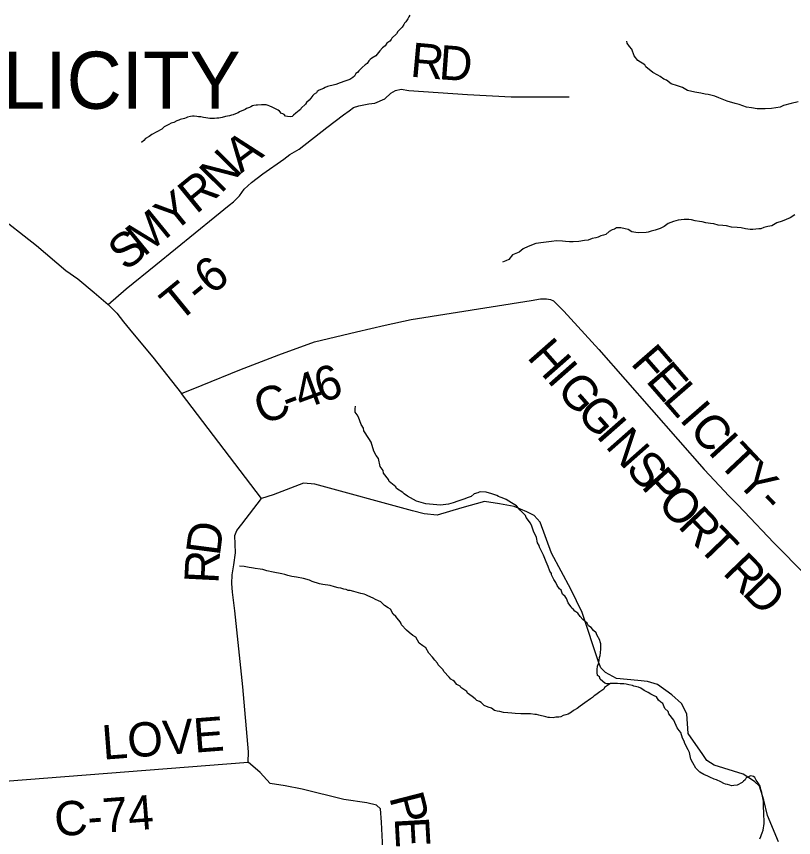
# Model space of a CAD drawing. Extents: x 1310247 to 1664935, y 235267 to 584339.
# Drawn here: x 1516027 to 1522829, y 302982 to 310168 of the extents above; entities that cross this region are included whole.
import ezdxf

# ---------------------------------------------------------------- set-up
doc = ezdxf.new("R2010")
doc.units = 0
for name, color, linetype in [('GM_X_Corporation_Text', 7, 'Continuous'), ('GM_X_County_Road', 7, 'Continuous'), ('GM_X_County_Road_Text', 7, 'Continuous'), ('GM_X_Minor_River', 7, 'Continuous'), ('GM_X_Township_Road', 7, 'Continuous'), ('GM_X_Township_Road_Text', 7, 'Continuous')]:
    doc.layers.add(name, color=color, linetype=linetype)

msp = doc.modelspace()

# ---------------------------------------------------------------- linework, layer by layer
at = {"layer": 'GM_X_County_Road'}
for points in [[(1515830, 308454), (1515834.2, 308450.8), (1516203.6, 308162.7), (1516460.4, 307945.9), (1516564.5, 307871.7), (1516707.1, 307751.9), (1516829.7, 307647.2), (1516905.4, 307570.7), (1516965.3, 307495.2), (1517043.7, 307398.2), (1517219.2, 307187), (1517470.2, 306867.6)], [(1517470.2, 306867.6), (1517651.3, 306940.3), (1517982.2, 307074.4), (1518324.6, 307205.6), (1518635.5, 307319.7), (1519003, 307408.2), (1519252.7, 307465.8), (1519482.6, 307516.8), (1520531.6, 307682.4), (1520613.6, 307695.7), (1520665, 307697.3), (1520701.4, 307690.6), (1520726.2, 307680), (1520817.9, 307588), (1521122.7, 307254.6), (1522045.4, 306204.2), (1522180.8, 306059.4), (1522260.7, 305974), (1522337.2, 305896.4), (1522396.1, 305834.8), (1522656.5, 305562.8), (1522936.1, 305279.3)], [(1518170.5, 305950.4), (1517470.2, 306867.6)], [(1522697.7, 302946.6), (1522600.7, 303174.8), (1522569.3, 303308.9), (1522529, 303431), (1522487.8, 303474.4), (1522386.7, 303537.1), (1522132.8, 303617), (1522069.4, 303656), (1522033, 303708.3), (1521904.6, 303893.7), (1521893.2, 304064.8), (1521847.5, 304155.6), (1521762, 304230.3), (1521636.5, 304321.6), (1521548.8, 304348.1), (1521465.3, 304355.8), (1521279.9, 304375.8), (1521182.9, 304427.1), (1521142.8, 304468), (1521123, 304512.7), (1520977.5, 304952), (1520879.9, 305155.8), (1520709.4, 305471.2), (1520609.5, 305742.2), (1520558, 305799.5), (1520492.6, 305833.5), (1520384.2, 305879.1), (1520255.8, 305901.9), (1520124.6, 305924.7), (1519924.9, 305867.7), (1519708.1, 305805), (1519594.7, 305814.2), (1519494.1, 305842), (1518638.4, 306076), (1518538.5, 306084.5), (1518273.2, 305981.8), (1518170.5, 305950.4)], [(1515927.5, 303476), (1518053.6, 303643.7), (1518056.6, 303733.7), (1518008.3, 304301.7), (1517938.3, 304965.4), (1517917.1, 305130.3), (1517912.7, 305205), (1517913.8, 305283), (1517930.5, 305368.8), (1517942.8, 305474.7), (1517937.4, 305626.6), (1517956.2, 305668.3), (1517999.4, 305725.7), (1518170.5, 305950.4)]]:
    msp.add_lwpolyline(points, dxfattribs=at)
at = {"layer": 'GM_X_Minor_River'}
for points in [[(1519471.2, 310178.1), (1519461, 310166.2), (1519452.8, 310146.2), (1519434.4, 310122.3), (1519424.2, 310108.4), (1519416, 310096.5), (1519403.7, 310074.5), (1519365.1, 310036.8), (1519352.8, 310014.9), (1519312.2, 309977.2), (1519306, 309965.2), (1519295.9, 309953.3), (1519269.5, 309933.5), (1519255.2, 309911.6), (1519230.9, 309893.8), (1519206.5, 309868), (1519171.8, 309822.3), (1519137.4, 309802.6), (1519123.3, 309792.8), (1519111.1, 309780.8), (1519096.7, 309756.9), (1519078.5, 309745.1), (1519054.1, 309721.3), (1519023.7, 309691.5), (1519011.4, 309677.6), (1518997.3, 309669.8), (1518987, 309645.8), (1518970.8, 309633.9), (1518944.4, 309616.2), (1518928.3, 309610.4), (1518902.1, 309602.6), (1518859.8, 309587.1), (1518821.4, 309573.5), (1518809.4, 309569.6), (1518748.9, 309554.3), (1518728.8, 309546.6), (1518714.6, 309538.7), (1518676.3, 309523.1), (1518658.1, 309511.3), (1518651.9, 309499.3), (1518633.7, 309487.5), (1518621.5, 309475.6), (1518603.1, 309453.7), (1518588.9, 309435.8), (1518566.5, 309414), (1518556.4, 309402), (1518519.8, 309366.3), (1518513.6, 309354.4), (1518501.5, 309344.5), (1518471, 309320.8), (1518452.8, 309304.9), (1518440.6, 309293), (1518424.5, 309289.2), (1518398.4, 309291.5), (1518382.4, 309295.7), (1518370.5, 309310), (1518358.5, 309316.1), (1518346.5, 309320.3), (1518330.7, 309338.6), (1518316.8, 309348.8), (1518264.9, 309375.5), (1518244.9, 309383.8), (1518228.9, 309390), (1518212.9, 309394.2), (1518172.7, 309394.8), (1518136.5, 309391.2), (1518124.5, 309391.3), (1518104.4, 309387.5), (1518092.3, 309385.7), (1518078.1, 309375.8), (1518066, 309370), (1518039.8, 309362.2), (1518027.6, 309354.4), (1517979.2, 309332.9), (1517967.1, 309325), (1517942.9, 309317.2), (1517924.7, 309307.4), (1517908.6, 309303.6), (1517890.4, 309299.8), (1517856.2, 309292.2), (1517828, 309282.5), (1517797.8, 309276.8), (1517779.7, 309277.1), (1517761.6, 309275.3), (1517719.5, 309275.8), (1517683.4, 309280.3), (1517665.4, 309284.5), (1517639.3, 309288.9)], [(1522870, 309420.7), (1522807.6, 309407.4), (1522741.1, 309388.1), (1522710.9, 309374.5), (1522634.4, 309361.3), (1522580.2, 309360), (1522509.9, 309358.9), (1522459.8, 309367.5), (1522417.7, 309374.1), (1522353.7, 309397), (1522317.6, 309407.5), (1522247.6, 309426.5), (1522173.6, 309455.5), (1522139.7, 309472), (1522079.6, 309484.8), (1522053.5, 309489.1), (1522015.5, 309495.6), (1521965.4, 309504.3), (1521901.3, 309519.1), (1521855.4, 309547.8), (1521813.4, 309560.4), (1521757.4, 309579.2), (1521717.6, 309611.8), (1521693.6, 309620.2), (1521661.8, 309642.6), (1521641.8, 309653), (1521597.9, 309677.6), (1521536.2, 309726.6), (1521526.4, 309744.8), (1521464.6, 309781.7), (1521433, 309822.3), (1521411.6, 309882.8), (1521391.8, 309905.1), (1521372, 309933.5), (1521370.2, 309951.6)], [(1517639.3, 309288.9), (1517619.2, 309291.1), (1517607.2, 309293.3), (1517583.2, 309295.6), (1517569.1, 309295.7), (1517549, 309294), (1517524.8, 309286.2), (1517512.7, 309282.4), (1517496.6, 309276.5), (1517460.3, 309267), (1517448.2, 309261.1), (1517430, 309253.3), (1517405.8, 309239.5), (1517381.6, 309233.8), (1517361.4, 309224), (1517321, 309202.4), (1517298.7, 309182.6), (1517211.8, 309135.5), (1517189.5, 309117.6), (1517157.1, 309100), (1517142.8, 309082.1), (1517122.6, 309064.2)], [(1522840.2, 308430.8), (1522797.8, 308407.3), (1522727.2, 308378), (1522680.8, 308362.5), (1522638.3, 308337), (1522604.1, 308331.4), (1522567.9, 308321.8), (1522541.6, 308310.1), (1522523.5, 308308.3), (1522499.4, 308306.6), (1522471.3, 308304.9), (1522449.2, 308305.2), (1522409.1, 308309.7), (1522369, 308318.2), (1522334.9, 308320.7), (1522284.7, 308325.3), (1522242.7, 308335.9), (1522210.6, 308338.3), (1522168.5, 308342.8), (1522130.4, 308353.4), (1522100.4, 308355.7), (1522060.3, 308362.3), (1522028.2, 308370.7), (1522004.2, 308375), (1521966.1, 308379.5), (1521936.1, 308387.9), (1521912, 308390.2), (1521871.8, 308390.7), (1521819.6, 308385.4), (1521777.3, 308373.8), (1521730.9, 308356.3), (1521696.4, 308330.7), (1521660.1, 308313), (1521633.8, 308303.3), (1521615.7, 308297.5), (1521581.5, 308287.9), (1521555.3, 308280.2), (1521537.2, 308278.4), (1521468.8, 308275.3), (1521446.8, 308277.5), (1521412.7, 308284), (1521380.8, 308302.5), (1521354.8, 308310.8), (1521316.7, 308317.3), (1521296.7, 308319.6), (1521278.6, 308317.8), (1521260.4, 308306), (1521242.2, 308300.2), (1521213.9, 308286.5), (1521185.5, 308260.7), (1521165.4, 308254.9), (1521141.2, 308247.2), (1521116.9, 308235.5), (1521096.8, 308229.7), (1521064.6, 308224.1), (1521030.3, 308210.4), (1520998.1, 308206.8), (1520947.8, 308199.4), (1520899.6, 308196), (1520867.5, 308196.4), (1520831.4, 308198.8), (1520805.3, 308201.2), (1520753.1, 308203.8), (1520708.9, 308198.4), (1520638.5, 308191.2), (1520574.1, 308180), (1520505.5, 308154.7), (1520463.1, 308135.1), (1520426.6, 308105.5), (1520398.4, 308093.8), (1520368.1, 308082.1), (1520337.5, 308042.3), (1520309.2, 308028.6), (1520281, 308018.9)], [(1521135.7, 304574.4), (1521140, 304598.5), (1521142.4, 304634.6), (1521142.7, 304656.7), (1521140.9, 304676.8), (1521137.1, 304694.9), (1521133.3, 304711), (1521105.7, 304755.5), (1521101.9, 304773.6), (1521076, 304794), (1521058.3, 304820.3), (1521034.4, 304836.7), (1521022.6, 304858.9), (1520984.8, 304891.5), (1520961, 304915.9), (1520941.3, 304946.3), (1520913.4, 304962.7), (1520903.5, 304978.9), (1520887.6, 304989.1), (1520881.7, 305001.2), (1520869.8, 305015.4), (1520856, 305035.7), (1520842.4, 305076), (1520828.6, 305092.2), (1520806.7, 305112.6), (1520793.1, 305146.9), (1520781.2, 305159.1), (1520759.4, 305187.5), (1520747.7, 305213.7), (1520729.9, 305242), (1520710.3, 305280.4), (1520708.5, 305292.5), (1520694.6, 305312.8), (1520681.1, 305355.1), (1520671.3, 305375.3), (1520663.5, 305395.5), (1520640.1, 305454), (1520628.3, 305476.2), (1520604.8, 305522.7), (1520600.9, 305538.8), (1520587.2, 305563.1), (1520577.7, 305607.4), (1520569.9, 305627.5), (1520554.1, 305653.8), (1520538.7, 305708.2), (1520524.9, 305732.5), (1520487.4, 305783.2), (1520481.6, 305801.3), (1520455.8, 305825.8), (1520435.9, 305848.1), (1520402.2, 305884.6), (1520358.4, 305911.3), (1520312.5, 305940), (1520278.6, 305956.5), (1520260.6, 305962.7), (1520244.6, 305966.9), (1520230.6, 305975.1), (1520186.6, 305989.7), (1520136.6, 306004.4), (1520092.5, 306009), (1520076.3, 306005.2), (1520064.2, 305999.3), (1520034, 305991.6), (1520005.6, 305967.9), (1519981.4, 305958.1), (1519941.1, 305942.6), (1519888.6, 305925.1), (1519850.3, 305911.6), (1519808, 305900), (1519785.9, 305896.3), (1519739.6, 305890.9), (1519611.3, 305902.5), (1519527.2, 305925.6), (1519449.4, 305970.8), (1519419.5, 305989.2), (1519409.6, 306001.4), (1519351.8, 306036.2), (1519346, 306052.3), (1519288.2, 306097.2), (1519284.4, 306115.4), (1519240.9, 306170.1), (1519235.2, 306194.3), (1519211.5, 306228.7), (1519194.3, 306299.2), (1519176.5, 306325.5), (1519154.9, 306364), (1519131.7, 306442.6), (1519112, 306474.9), (1519068.6, 306541.8), (1519064.9, 306563.9), (1519043.2, 306596.3), (1519021.8, 306660.8), (1519008, 306681.1), (1518992.3, 306705.4), (1518992.6, 306735.5), (1518994.9, 306757.5)], [(1518479, 305259.9), (1518437, 305268.4), (1518400.9, 305274.9), (1518374.9, 305285.3), (1518350.9, 305289.6), (1518272.7, 305304.6), (1518218.7, 305317.3), (1518184.7, 305327.8), (1518160.6, 305332.1), (1518116.5, 305336.6), (1518100.4, 305338.8), (1518084.4, 305343), (1518064.4, 305347.3), (1518034.3, 305351.7), (1518020.3, 305353.9), (1517980.2, 305356.4)], [(1521227.1, 304330.3), (1521174.5, 304294.9), (1521168.3, 304280.9), (1521131.9, 304257.2), (1521097.4, 304231.6), (1521083.3, 304221.7), (1521069, 304207.8), (1521050.8, 304198), (1521000.2, 304160.5), (1520961.7, 304132.9), (1520933.3, 304111.1), (1520901, 304093.5), (1520884.8, 304079.6), (1520854.4, 304061.9), (1520834.3, 304056.2), (1520812.1, 304050.4), (1520791.9, 304038.6), (1520773.8, 304036.8), (1520747.7, 304035.2), (1520723.5, 304031.4), (1520691.4, 304031.8), (1520679.4, 304034), (1520659.4, 304038.3), (1520637.3, 304044.5), (1520623.3, 304048.7), (1520599.3, 304053.1), (1520577.3, 304059.4), (1520563.2, 304059.5), (1520527.1, 304064), (1520442.8, 304065), (1520392.6, 304067.7), (1520362.5, 304070), (1520328.4, 304074.5), (1520290.3, 304077), (1520256.3, 304085.4), (1520234.2, 304089.7), (1520210.2, 304094), (1520184.3, 304114.4), (1520156.3, 304122.8), (1520120.3, 304137.3), (1520094.6, 304163.7), (1520078.6, 304172), (1520056.6, 304182.3), (1520040.7, 304196.5), (1520014.9, 304216.9), (1519975.1, 304247.5), (1519969.2, 304261.6), (1519915.4, 304296.4), (1519909.5, 304308.6), (1519881.6, 304323), (1519861.8, 304347.3), (1519847.9, 304357.5), (1519827.9, 304369.8), (1519814.1, 304386), (1519768.5, 304436.8), (1519762.6, 304450.9), (1519717, 304493.6), (1519713.1, 304509.8), (1519687.3, 304536.2), (1519667.5, 304560.5), (1519635.8, 304597), (1519610.3, 304643.5), (1519584.4, 304659.9), (1519550.5, 304684.4), (1519523, 304735), (1519497.1, 304751.4), (1519463.3, 304775.9), (1519441.4, 304796.2), (1519397.8, 304845), (1519394, 304857), (1519384.1, 304871.2), (1519358.4, 304903.7), (1519348.5, 304917.8), (1519324.6, 304936.2), (1519301, 304980.7), (1519279.1, 304993), (1519249.2, 305013.4), (1519217.5, 305046), (1519195.5, 305054.2), (1519169.5, 305066.6), (1519149.6, 305076.9), (1519103.6, 305097.5), (1519083.7, 305107.8), (1519071.7, 305112), (1519041.6, 305118.4), (1519019.6, 305124.7), (1518979.6, 305135.2), (1518947.6, 305143.7), (1518931.5, 305145.9), (1518913.5, 305152.1), (1518891.5, 305156.4), (1518867.5, 305164.7), (1518841.4, 305169.1), (1518809.4, 305175.5), (1518773.4, 305188), (1518709.2, 305196.8), (1518679.2, 305203.2), (1518615.1, 305222), (1518591.2, 305234.4), (1518539.2, 305249.1), (1518479, 305259.9)], [(1522532.3, 302971), (1522540.5, 302991), (1522548.8, 303008.9), (1522555, 303024.9), (1522561.3, 303046.9), (1522570, 303105), (1522570.3, 303127.1), (1522568.9, 303183.3), (1522567.2, 303203.4), (1522567.3, 303217.5), (1522565.5, 303235.6), (1522566.1, 303279.7), (1522564.3, 303299.8), (1522553, 303360.2), (1522551.2, 303378.3), (1522541.4, 303402.5), (1522535.8, 303432.7), (1522516.1, 303465), (1522502.3, 303485.3), (1522490.5, 303509.5), (1522478.5, 303515.7), (1522466.5, 303519.9), (1522452.5, 303524.1), (1522412.1, 303504.5), (1522403.9, 303488.5), (1522389.7, 303476.7), (1522377.5, 303464.8), (1522335.1, 303441.2), (1522306.9, 303437.5), (1522284.8, 303435.8), (1522270.8, 303440), (1522248.8, 303446.3), (1522232.8, 303450.5), (1522216.8, 303456.7), (1522190.8, 303471.1), (1522154.9, 303487.6), (1522134.9, 303493.9), (1522096.9, 303512.4), (1522076.9, 303518.7), (1522043, 303533.2), (1522009.1, 303555.7), (1521973.4, 303590.3), (1521945.8, 303636.8), (1521930.1, 303669.1), (1521918.8, 303725.5), (1521907, 303749.7), (1521875.5, 303806.3), (1521871.8, 303826.4), (1521856, 303852.7), (1521840.5, 303901.1), (1521826.7, 303919.3), (1521808.9, 303941.6), (1521779.6, 304010.3), (1521736, 304065), (1521730.3, 304085.2), (1521702.5, 304111.6), (1521682.9, 304156), (1521667, 304168.3), (1521645.1, 304184.6), (1521627.4, 304212.9), (1521609.4, 304223.2), (1521579.5, 304237.6), (1521555.5, 304252), (1521519.6, 304270.5), (1521491.7, 304290.9), (1521471.7, 304297.2), (1521431.7, 304307.7), (1521417.7, 304313.9), (1521387.7, 304320.3), (1521363.6, 304324.6), (1521341.6, 304326.9), (1521311.4, 304327.3), (1521287.4, 304329.6), (1521227.1, 304330.3), (1521213, 304328.5), (1521193, 304328.8), (1521177, 304335), (1521159.1, 304349.3), (1521137.2, 304369.6), (1521129.4, 304387.8), (1521113.5, 304402), (1521109.8, 304426.2), (1521110.1, 304452.3), (1521112.5, 304482.3), (1521122.9, 304512.3), (1521129.4, 304558.4), (1521135.7, 304574.4)]]:
    msp.add_lwpolyline(points, dxfattribs=at)
at = {"layer": 'GM_X_Township_Road'}
for points in [[(1516829.7, 307647.2), (1516987.4, 307785), (1517245.7, 307995.4), (1517764.4, 308415.4), (1517889.1, 308516.1), (1517926, 308547.1), (1517978.9, 308597.9), (1518020.8, 308657.8), (1518084.6, 308714.6), (1518182.3, 308791.4), (1518367.3, 308919.9), (1518418.7, 308960), (1518502.5, 309005.9), (1518743.9, 309197.4), (1518890.5, 309308.1), (1518939.4, 309342), (1518978.3, 309370), (1519024.2, 309384.9), (1519110, 309402.9), (1519164, 309409.6), (1519249.7, 309447.6), (1519302.5, 309496.6), (1519345.4, 309521.6), (1519395.3, 309532.6), (1519461.1, 309520.6), (1519973.8, 309483.7), (1520357.8, 309463.7), (1520677, 309465.7), (1520865.5, 309465.7)], [(1519270.6, 301524.5), (1519277.7, 301555.2), (1519289.3, 301633.6), (1519277.7, 301803.6), (1519237, 302824.8), (1519222.5, 303116.8), (1519212.3, 303234.5), (1519178.9, 303266.4), (1519093.2, 303286.8), (1518891.1, 303315), (1518527.9, 303406.8), (1518378.5, 303434.9), (1518247.8, 303456.7), (1518158.8, 303552.7), (1518053.6, 303643.7)]]:
    msp.add_lwpolyline(points, dxfattribs=at)

# ---------------------------------------------------------------- texts
at = {"layer": 'GM_X_Corporation_Text'}
msp.add_text('FELICITY', height=500, rotation=0.00001, dxfattribs=at).set_placement((1515053.9, 309360.2))
at = {"layer": 'GM_X_County_Road_Text'}
for s, rotation, p in [('H', 311.3631, (1520487.3, 307183.6)), ('F', 311.03731, (1521394.4, 307130.3)), ('I', 311.35739, (1520661.8, 306985.4)), ('E', 311.03932, (1521527.3, 306977.6)), ('4', 20.13272, (1518521.2, 306721.2)), ('6', 18.105, (1518692.1, 306783.9)), ('G', 311.36299, (1520743.2, 306892.9)), ('C', 20.6305, (1518175.9, 306591.4)), ('L', 311.03915, (1521674.6, 306808.4)), ('-', 20.53229, (1518406.4, 306678.2)), ('G', 311.35916, (1520917.7, 306694.8)), ('I', 311.0365, (1521821.9, 306639.1)), ('I', 311.35739, (1521092.1, 306496.7)), ('C', 311.30216, (1521903.8, 306545.1)), ('N', 311.43734, (1521173.8, 306403.8)), ('I', 312.36207, (1522070.5, 306355.4)), ('T', 313.2947, (1522157.1, 306260.5)), ('S', 311.76835, (1521349.8, 306204.5)), ('Y', 313.92124, (1522313.5, 306094.6)), ('P', 312.38184, (1521486.9, 306050.9)), ('O', 312.80944, (1521625, 305899.6)), ('-', 313.93574, (1522496.6, 305904.4)), ('R', 313.53175, (1521807.3, 305702.9)), ('D', 82.59913, (1517806.6, 305440.7)), ('T', 313.93446, (1521978.6, 305522.6)), ('R', 314.03224, (1522198.9, 305294.2)), ('R', 87.14967, (1517794.9, 305200.9)), ('D', 314.03016, (1522370.1, 305117.1)), ('LOVE', 4.37902, (1516786.3, 303663.7)), ('C-74', 4.47814, (1516369.7, 302991.2))]:
    msp.add_text(s, height=300, rotation=rotation, dxfattribs=at).set_placement(p)
at = {"layer": 'GM_X_Township_Road_Text'}
for s, rotation, p in [('R', 354.79815, (1519467.2, 309642.4)), ('D', 355.79611, (1519718.2, 309619.6)), ('A', 36.96024, (1517992.4, 308791.6)), ('N', 45.26425, (1517815.2, 308611.6)), ('R', 39.29185, (1517599.3, 308432.6)), ('Y', 39.17751, (1517394.1, 308265.5)), ('M', 39.17251, (1517141.7, 308059.8)), ('S', 39.17406, (1516984.8, 307931.9)), ('T-6', 39.32016, (1517445, 307484)), ('P', 284.44997, (1519288.6, 303335.8)), ('E', 273.19446, (1519336.7, 303155.2))]:
    msp.add_text(s, height=300, rotation=rotation, dxfattribs=at).set_placement(p)

doc.saveas('drawing.dxf')
